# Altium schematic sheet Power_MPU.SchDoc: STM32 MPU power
size A3; Date: Not used; ApprovedBy: Not used; CheckedBy: Not used; Author: Not used; CompanyName: STMicroelectronics; DrawnBy: Not used; Engineer: Not used; Organization: Not used; Address1: Not used; Address2: Not used; Address3: Not used; Address4: Not used; DocumentNumber: 4; Revision: Not used; SheetNumber: 4; SheetTotal: 17
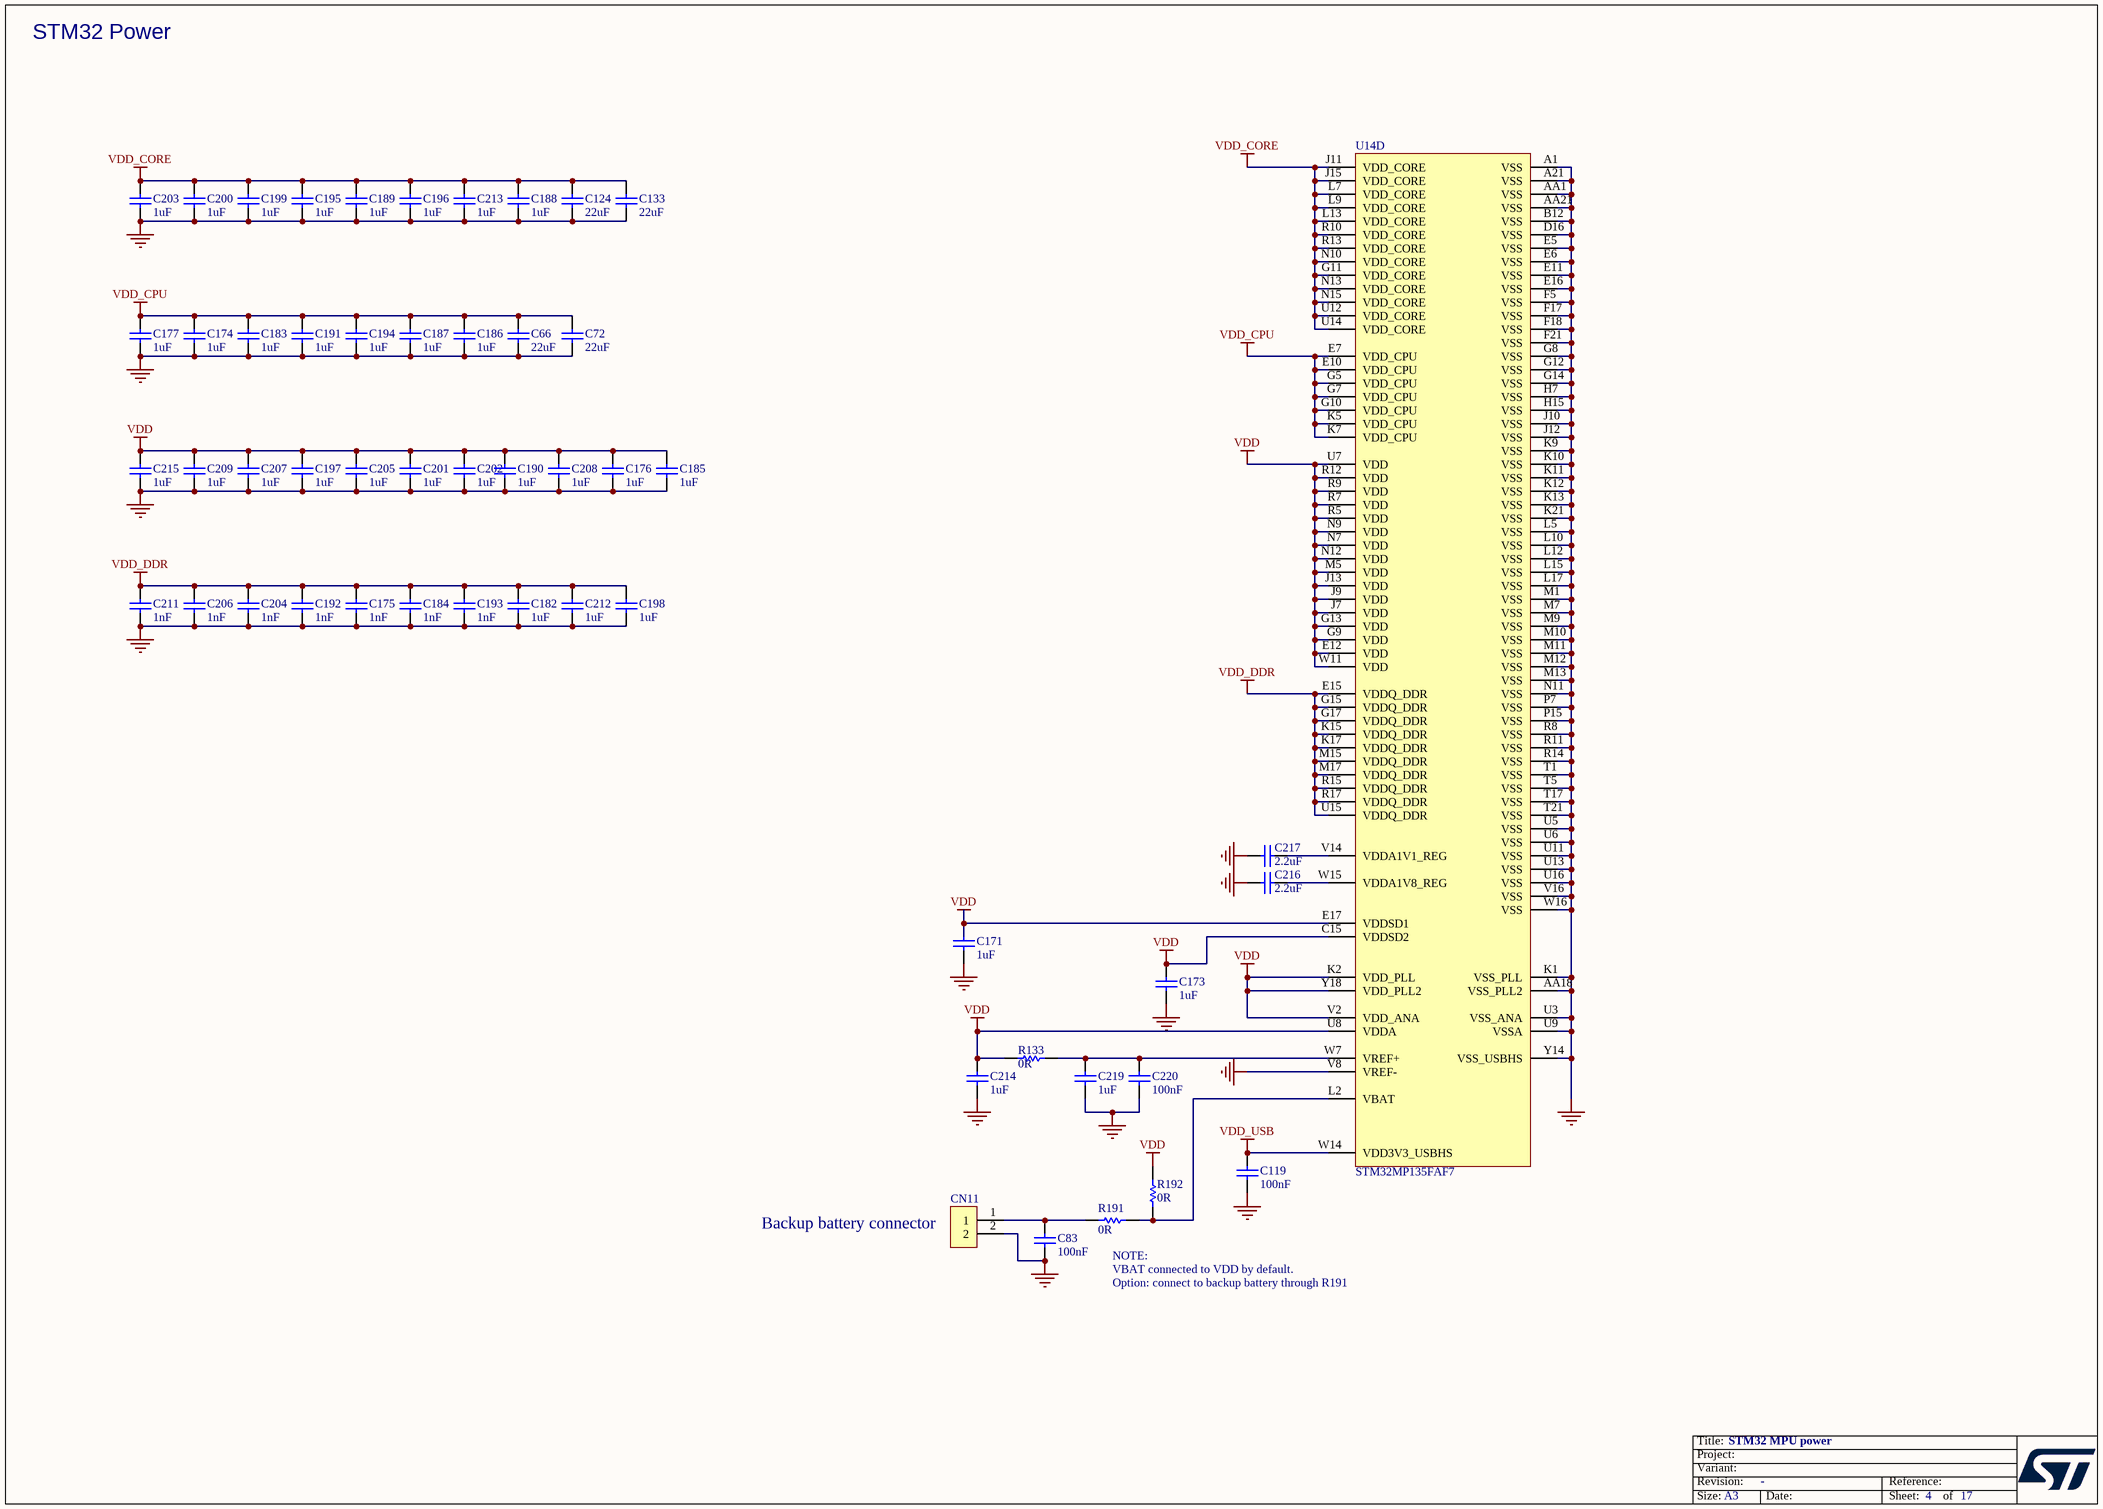
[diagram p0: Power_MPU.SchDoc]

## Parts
C66  value 22uF  [C0603]  (hidden comment: Capacitor)
C72  value 22uF  [C0603]  (hidden comment: Capacitor)
C83  value 100nF  [C0402]  (hidden comment: Capacitor)
C119  value 100nF  [C0402]  (hidden comment: Capacitor)
C124  value 22uF  [C0603]  (hidden comment: Capacitor)
C133  value 22uF  [C0603]  (hidden comment: Capacitor)
C171  value 1uF  [C0201_MURATA_GRM033_H0P3]  (hidden comment: Capacitor)
C173  value 1uF  [C0201_MURATA_GRM033_H0P3]  (hidden comment: Capacitor)
C174  value 1uF  [C0201_MURATA_GRM033_H0P3]  (hidden comment: Capacitor)
C175  value 1nF  [C0201_MURATA_GRM033_H0P3]  (hidden comment: Capacitor)
C176  value 1uF  [C0201_MURATA_GRM033_H0P3]  (hidden comment: Capacitor)
C177  value 1uF  [C0201_MURATA_GRM033_H0P3]  (hidden comment: Capacitor)
C182  value 1uF  [C0201_MURATA_GRM033_H0P3]  (hidden comment: Capacitor)
C183  value 1uF  [C0201_MURATA_GRM033_H0P3]  (hidden comment: Capacitor)
C184  value 1nF  [C0201_MURATA_GRM033_H0P3]  (hidden comment: Capacitor)
C185  value 1uF  [C0201_MURATA_GRM033_H0P3]  (hidden comment: Capacitor)
C186  value 1uF  [C0201_MURATA_GRM033_H0P3]  (hidden comment: Capacitor)
C187  value 1uF  [C0201_MURATA_GRM033_H0P3]  (hidden comment: Capacitor)
C188  value 1uF  [C0201_MURATA_GRM033_H0P3]  (hidden comment: Capacitor)
C189  value 1uF  [C0201_MURATA_GRM033_H0P3]  (hidden comment: Capacitor)
C190  value 1uF  [C0201_MURATA_GRM033_H0P3]  (hidden comment: Capacitor)
C191  value 1uF  [C0201_MURATA_GRM033_H0P3]  (hidden comment: Capacitor)
C192  value 1nF  [C0201_MURATA_GRM033_H0P3]  (hidden comment: Capacitor)
C193  value 1nF  [C0201_MURATA_GRM033_H0P3]  (hidden comment: Capacitor)
C194  value 1uF  [C0201_MURATA_GRM033_H0P3]  (hidden comment: Capacitor)
C195  value 1uF  [C0201_MURATA_GRM033_H0P3]  (hidden comment: Capacitor)
C196  value 1uF  [C0201_MURATA_GRM033_H0P3]  (hidden comment: Capacitor)
C197  value 1uF  [C0201_MURATA_GRM033_H0P3]  (hidden comment: Capacitor)
C198  value 1uF  [C0201_MURATA_GRM033_H0P3]  (hidden comment: Capacitor)
C199  value 1uF  [C0201_MURATA_GRM033_H0P3]  (hidden comment: Capacitor)
C200  value 1uF  [C0201_MURATA_GRM033_H0P3]  (hidden comment: Capacitor)
C201  value 1uF  [C0201_MURATA_GRM033_H0P3]  (hidden comment: Capacitor)
C202  value 1uF  [C0201_MURATA_GRM033_H0P3]  (hidden comment: Capacitor)
C203  value 1uF  [C0201_MURATA_GRM033_H0P3]  (hidden comment: Capacitor)
C204  value 1nF  [C0201_MURATA_GRM033_H0P3]  (hidden comment: Capacitor)
C205  value 1uF  [C0201_MURATA_GRM033_H0P3]  (hidden comment: Capacitor)
C206  value 1nF  [C0201_MURATA_GRM033_H0P3]  (hidden comment: Capacitor)
C207  value 1uF  [C0201_MURATA_GRM033_H0P3]  (hidden comment: Capacitor)
C208  value 1uF  [C0201_MURATA_GRM033_H0P3]  (hidden comment: Capacitor)
C209  value 1uF  [C0201_MURATA_GRM033_H0P3]  (hidden comment: Capacitor)
C211  value 1nF  [C0201_MURATA_GRM033_H0P3]  (hidden comment: Capacitor)
C212  value 1uF  [C0201_MURATA_GRM033_H0P3]  (hidden comment: Capacitor)
C213  value 1uF  [C0201_MURATA_GRM033_H0P3]  (hidden comment: Capacitor)
C214  value 1uF  [C0201_MURATA_GRM033_H0P3]  (hidden comment: Capacitor)
C215  value 1uF  [C0201_MURATA_GRM033_H0P3]  (hidden comment: Capacitor)
C216  value 2.2uF  [C0201_H0P5]  (hidden comment: Capacitor)
C217  value 2.2uF  [C0201_H0P5]  (hidden comment: Capacitor)
C219  value 1uF  [C0201_MURATA_GRM033_H0P3]  (hidden comment: Capacitor)
C220  value 100nF  [C0402]  (hidden comment: Capacitor)
CN11  Header 2x1  [CON_MOLEX_53047-0210]  (value not drawn)
R133  value 0R  [R0402]  (hidden comment: Resistor)
R191  value 0R  [R0402]  (hidden comment: Resistor)
R192  value 0R  [R0402]  (hidden comment: Resistor)
U14  STM32MP135FAF7  [ICC_TFBGA320_11X11_STM32MP135FA7_P050_H1P20]  (part D of 5)

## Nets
GND: C66.1 C72.1 C83.1 C119.1 C124.1 C133.1 C171.1 C173.1 C174.1 C175.1 C176.1 C177.2 C182.1 C183.1 C184.1 C185.2 C186.1 C187.1 C188.1 C189.1 C190.1 C191.2 C192.1 C193.1 C194.1 C195.2 C196.1 C197.1 C198.1 C199.1 C200.1 C201.1 C202.1 C203.2 C204.2 C205.1 C206.1 C207.2 C208.1 C209.1 C211.1 C212.1 C213.1 C214.2 C215.2 C216.2 C217.2 C219.2 C220.1 CN11.2 U14.A1(VSS) U14.A21(VSS) U14.AA1(VSS) U14.AA18(VSS_PLL2) U14.AA21(VSS) U14.B12(VSS) U14.D16(VSS) U14.E5(VSS) U14.E6(VSS) U14.E11(VSS) U14.E16(VSS) U14.F5(VSS) U14.F17(VSS) U14.F18(VSS) U14.F21(VSS) U14.G8(VSS) U14.G12(VSS) U14.G14(VSS) U14.H7(VSS) U14.H15(VSS) U14.J10(VSS) U14.J12(VSS) U14.K1(VSS_PLL) U14.K9(VSS) U14.K10(VSS) U14.K11(VSS) U14.K12(VSS) U14.K13(VSS) U14.K21(VSS) U14.L5(VSS) U14.L10(VSS) U14.L12(VSS) U14.L15(VSS) U14.L17(VSS) U14.M1(VSS) U14.M7(VSS) U14.M9(VSS) U14.M10(VSS) U14.M11(VSS) U14.M12(VSS) U14.M13(VSS) U14.N11(VSS) U14.P7(VSS) U14.P15(VSS) U14.R8(VSS) U14.R11(VSS) U14.R14(VSS) U14.T1(VSS) U14.T5(VSS) U14.T17(VSS) U14.T21(VSS) U14.U3(VSS_ANA) U14.U5(VSS) U14.U6(VSS) U14.U9(VSSA) U14.U11(VSS) U14.U13(VSS) U14.U16(VSS) U14.V8(VREF-) U14.V16(VSS) U14.W16(VSS) U14.Y14(VSS_USBHS)
VDD: C171.2 C173.2 C176.2 C185.1 C190.2 C197.2 C201.2 C202.2 C205.2 C207.1 C208.2 C209.2 C214.1 C215.1 R133.2 R192.2 U14.C15(VDDSD2) U14.E12(VDD) U14.E17(VDDSD1) U14.G9(VDD) U14.G13(VDD) U14.J7(VDD) U14.J9(VDD) U14.J13(VDD) U14.K2(VDD_PLL) U14.M5(VDD) U14.N7(VDD) U14.N9(VDD) U14.N12(VDD) U14.R5(VDD) U14.R7(VDD) U14.R9(VDD) U14.R12(VDD) U14.U7(VDD) U14.U8(VDDA) U14.V2(VDD_ANA) U14.W11(VDD) U14.Y18(VDD_PLL2)
VDD_CORE: C124.2 C133.2 C188.2 C189.2 C195.1 C196.2 C199.2 C200.2 C203.1 C213.2 U14.G11(VDD_CORE) U14.J11(VDD_CORE) U14.J15(VDD_CORE) U14.L7(VDD_CORE) U14.L9(VDD_CORE) U14.L13(VDD_CORE) U14.N10(VDD_CORE) U14.N13(VDD_CORE) U14.N15(VDD_CORE) U14.R10(VDD_CORE) U14.R13(VDD_CORE) U14.U12(VDD_CORE) U14.U14(VDD_CORE)
VDD_CPU: C66.2 C72.2 C174.2 C177.1 C183.2 C186.2 C187.2 C191.1 C194.2 U14.E7(VDD_CPU) U14.E10(VDD_CPU) U14.G5(VDD_CPU) U14.G7(VDD_CPU) U14.G10(VDD_CPU) U14.K5(VDD_CPU) U14.K7(VDD_CPU)
VDD_DDR: C175.2 C182.2 C184.2 C192.2 C193.2 C198.2 C204.1 C206.2 C211.2 C212.2 U14.E15(VDDQ_DDR) U14.G15(VDDQ_DDR) U14.G17(VDDQ_DDR) U14.K15(VDDQ_DDR) U14.K17(VDDQ_DDR) U14.M15(VDDQ_DDR) U14.M17(VDDQ_DDR) U14.R15(VDDQ_DDR) U14.R17(VDDQ_DDR) U14.U15(VDDQ_DDR)
VDD_USB: C119.2 U14.W14(VDD3V3_USBHS)
NetC83_2: C83.2 CN11.1 R191.2
NetC216_1: C216.1 U14.W15(VDDA1V8_REG)
NetC217_1: C217.1 U14.V14(VDDA1V1_REG)
NetC219_1: C219.1 C220.2 R133.1 U14.W7(VREF+)
NetR191_1: R191.1 R192.1 U14.L2(VBAT)

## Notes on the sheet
- STM32 Power
- (near CN11) Backup battery connector
- NOTE:
  VBAT connected to VDD by default.
  Option: connect to backup battery through R191

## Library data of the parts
C66 C72 C124 C133 = MCD-00100: Capacitor, MLCC, 22uF, 6V3, X5R, +/-20%, 0603, T=0.8mm; Part_Preference: Recommended; Manufacturer: MURATA; Manufacturer_Part_Number: GRM188R60J226MEA0; Partial_Alternate_Internal_Part_Number: MCD-04184; Component_Country_Of_Origin: Japan°°; ShowFields: YES; ID: 2766
C83 C119 C220 = MCD-00006: Capacitor, MLCC, 100nF, 16V, X7R, +/-10%, 0402, T=0.5mm; Manufacturer_Part_Number: CC0402KRX7R7BB104; Manufacturer: YAGEO; Part_Preference: Recommended; Partial_Alternate_Internal_Part_Number: MCD-03299; Order_Code_RS: 9402047; Component_Country_Of_Origin: China; ShowFields: YES; ID: 2474
C171 C173 C174 C176 C177 C182 C183 C185-C191 C194-C203 C205 C207-C209 C212-C215 C219 = MCD-02377: Capacitor, MLCC, 1uF, 6.3V, X5R, +/-20%, 0201, T=0,3mm; Part_Preference: Recommended; Manufacturer: MURATA; Manufacturer_Part_Number: GRM033R60J105MEA2; Partial_Alternate_Internal_Part_Number: MCD-04356; Order_Code_RS: 820-0643; Component_Country_Of_Origin: Japan°; ShowFields: YES; ID: 4483
C175 C184 C192 C193 C204 C206 C211 = MCD-01729: Capacitor, MLCC, 1nF, 25V, X7R,+/-5%, 0201,T=0.3mm; Part_Preference: Recommended; Manufacturer: MURATA; Manufacturer_Part_Number: GRM033R71E102JA01; Order_Code_RS: 185-1954; Component_Country_Of_Origin: Japan°°; ShowFields: YES; ID: 3829
C216 C217 = MCD-02235: Capacitor, MLCC, 2.2uF, 10V, X5R,+/-10%, 0201, T=0.5mm; Manufacturer_Part_Number: GRM033R61A225KE47; Manufacturer: MURATA; Part_Preference: Recommended; Order_Code_RS: NA; Component_Country_Of_Origin: Japan°°; ShowFields: YES; ID: 4335
CN11 = MCD-00655: Header, 2x1, 1.25mm, VR, TH, T=2.25mm/2.3mm; Part_Type: Connector; Manufacturer_Part_Number: 53047-0210; Manufacturer: MOLEX; BMS_Part_Number: 9083002; Part_Preference: Recommended; Partial_Alternate_Internal_Part_Number: MCD-04371, MCD-04208; Value: Shrouded_53047-0210; Order_Code_RS: 279-9213; Component_Country_Of_Origin: Unknown; ShowFields: YES; ID: 3091
R133 R191 R192 = MCD-00052: Resistor, 0R, 0402, +/-5%, 1/16W; Manufacturer_Part_Number: RC0402JR-070RL; Manufacturer: YAGEO; Part_Preference: Recommended; Order_Code_RS: 9232516RL; Component_Country_Of_Origin: China; ShowFields: YES; ID: 2540
U14 = MCD-02251: Cortex-A7 @ 900MHz, 128KB-ROM, 128KB-SRAM, 2x Ethernet, 2x ADC, 2x CAN FD, TSC, Camera, Display, Secure Boot, Cryptography, DRAM enc/dec, PKA; Part_Preference: Recommended; Part_Type: IC; Manufacturer: STMICROELECTRONICS; Manufacturer_HQ_COO: EU; Component_Country_Of_Origin: Unknown; ShowFields: YES; ID: 4351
